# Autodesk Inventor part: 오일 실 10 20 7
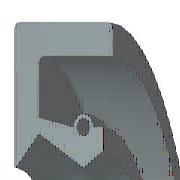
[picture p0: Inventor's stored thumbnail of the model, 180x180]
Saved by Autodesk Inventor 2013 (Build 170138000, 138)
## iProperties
IsCustomPart: 1
Created: 2012-02
Part Number: 오일 실 10 20 7
Material: 고무
Description: 오일-실
Document SubType Name: Modeling
Standard: KS B 2804
Designer: mduedu
Standards Organization: KS
Language: ko-KR
Size Designation: D - 10 20 7
Categories: <MemberInstance><Categories><Category DisplayName="샤프트 부품" InternalName="7f7aeb1f-a693-4053-b835-cee3144e0d98" Mnemonic="SHFT"><Category DisplayName="실링" Intern
Density: 0.93 g/cm^3
Mass: 1.11329 g
Surface Area: 16.3871 cm^2
Volume: 1.19708 cm^3
Author: mduedu
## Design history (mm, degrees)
revolve "본체" stored, may be unused: angle "d17" = 90 deg
revolve "스프링1" stored, may be unused: angle "d18" = 90 deg
body "Solid1"
sketch "스케치1"
  geometry: L1 (0, 10)-(7, 10); L2 (7, 8.25)-(1.75, 8.25); L3 (1.75, 6.75)-(4.9, 5); L4 (4.9, 5)-(0, 5); L5 (0, 0)-(9.586, 0) reference; L6 (4.9, 5)-(6.3, 5.875); L7 (0, 18)-(0, -3) reference; L8 (-1.941, 0)-(11.507, 0) reference; L9 (4.2, 7.1)-(1.75, 7.59); L10 (1.75, 7.59)-(1.75, 8.25); L11 (0, 10)-(0, 5.088); L12 (4.9, 5)-(0, 5); L13 (1.75, 6.75)-(0.152, 5.028); L14 (7, 10)-(7, 8.25); L15 (5.6, 7.1)-(6.3, 7.1); L16 (6.3, 7.1)-(6.3, 5.875); C1 r 0.455 at (4.9, 7.1); A1 r 0.7 centre (4.9, 7.1) between (5.6, 7.1) and (4.2, 7.1); A2 r 0.088 centre (0.088, 5.088) between (0, 5.088) and (0.152, 5.028); 1 further point
  constraints: 28 end point, 5 horizontal alignment, 5 point on line, 4 point on circle, 4 vertical alignment, 3 centre point, 3 tangent, 2 collinear, 2 horizontal, 2 perpendicular, 1 coincident, 1 parallel
  dimensions: "d0" = 20 diameter of L1 L5 (= SD2); "d1" = 1.75 distance of L1.end L2.start (= SD); "d2" = 0.91 diameter of C1 (= SPDI); "d3" = 1.4 diameter of A1 (= SPDA); "d4" = 10 diameter of L3.end L5 (= NND); "d5" = 13.5 diameter of L3.start L5 (= TKDM); "d7" = 15.18 diameter of L9.end L5 (= TKDM + 0.24 x SWDT); "d8" = 1.75 distance between parallel lines of L11 L10 (= SD); "d9" = 4.9 distance from line of L11 C1.centre (= SPDST); "d10" = 14.2 diameter of C1.centre L5 (= HLDM); "d11" = 0.0875 radius of A2 (= 0.25 x LAB); "d12" = 6.3 distance between parallel lines of L11 L16 (= SDI); "d13" = 11.75 diameter of L6.end L5 (= ABDM); "d14" = 7 distance from line of L11 L1.end (= SWDT)
fillet "모깎기1" dims "d6" = 0.3 (= RR)
other parameters: "SD2" = 20 [user parameter; used in 1 equation term], "SWDT" = 7 [user parameter; used in 2 equation terms], "RR" = 0.3 [user parameter; used in 1 equation term], "SD" = 1.75 [user parameter; used in 2 equation terms], "NND" = 10 [user parameter; used in 1 equation term], "SPDA" = 1.4 [user parameter; used in 1 equation term], "SPDI" = 0.91 [user parameter; used in 1 equation term], "TKDM" = 13.5 [user parameter; used in 2 equation terms], "HLDM" = 14.2 [user parameter; used in 1 equation term], "ABDM" = 11.75 [user parameter; used in 1 equation term], "SDI" = 6.3 [user parameter; used in 1 equation term], "SPDST" = 4.9 [user parameter; used in 1 equation term], "LAB" = 0.35 [user parameter; used in 1 equation term], "d15" = 0, "d16" = 0, "d19" = 0
